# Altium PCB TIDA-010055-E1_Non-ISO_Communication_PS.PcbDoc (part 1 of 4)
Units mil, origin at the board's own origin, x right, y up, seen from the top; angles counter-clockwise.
Board outline 3937.01 x 3346.46 mil, 2 copper layers (Top Layer, Bottom Layer), stack 62 mil thick; 328 components, 142 nets, 761 pads, 214 vias.
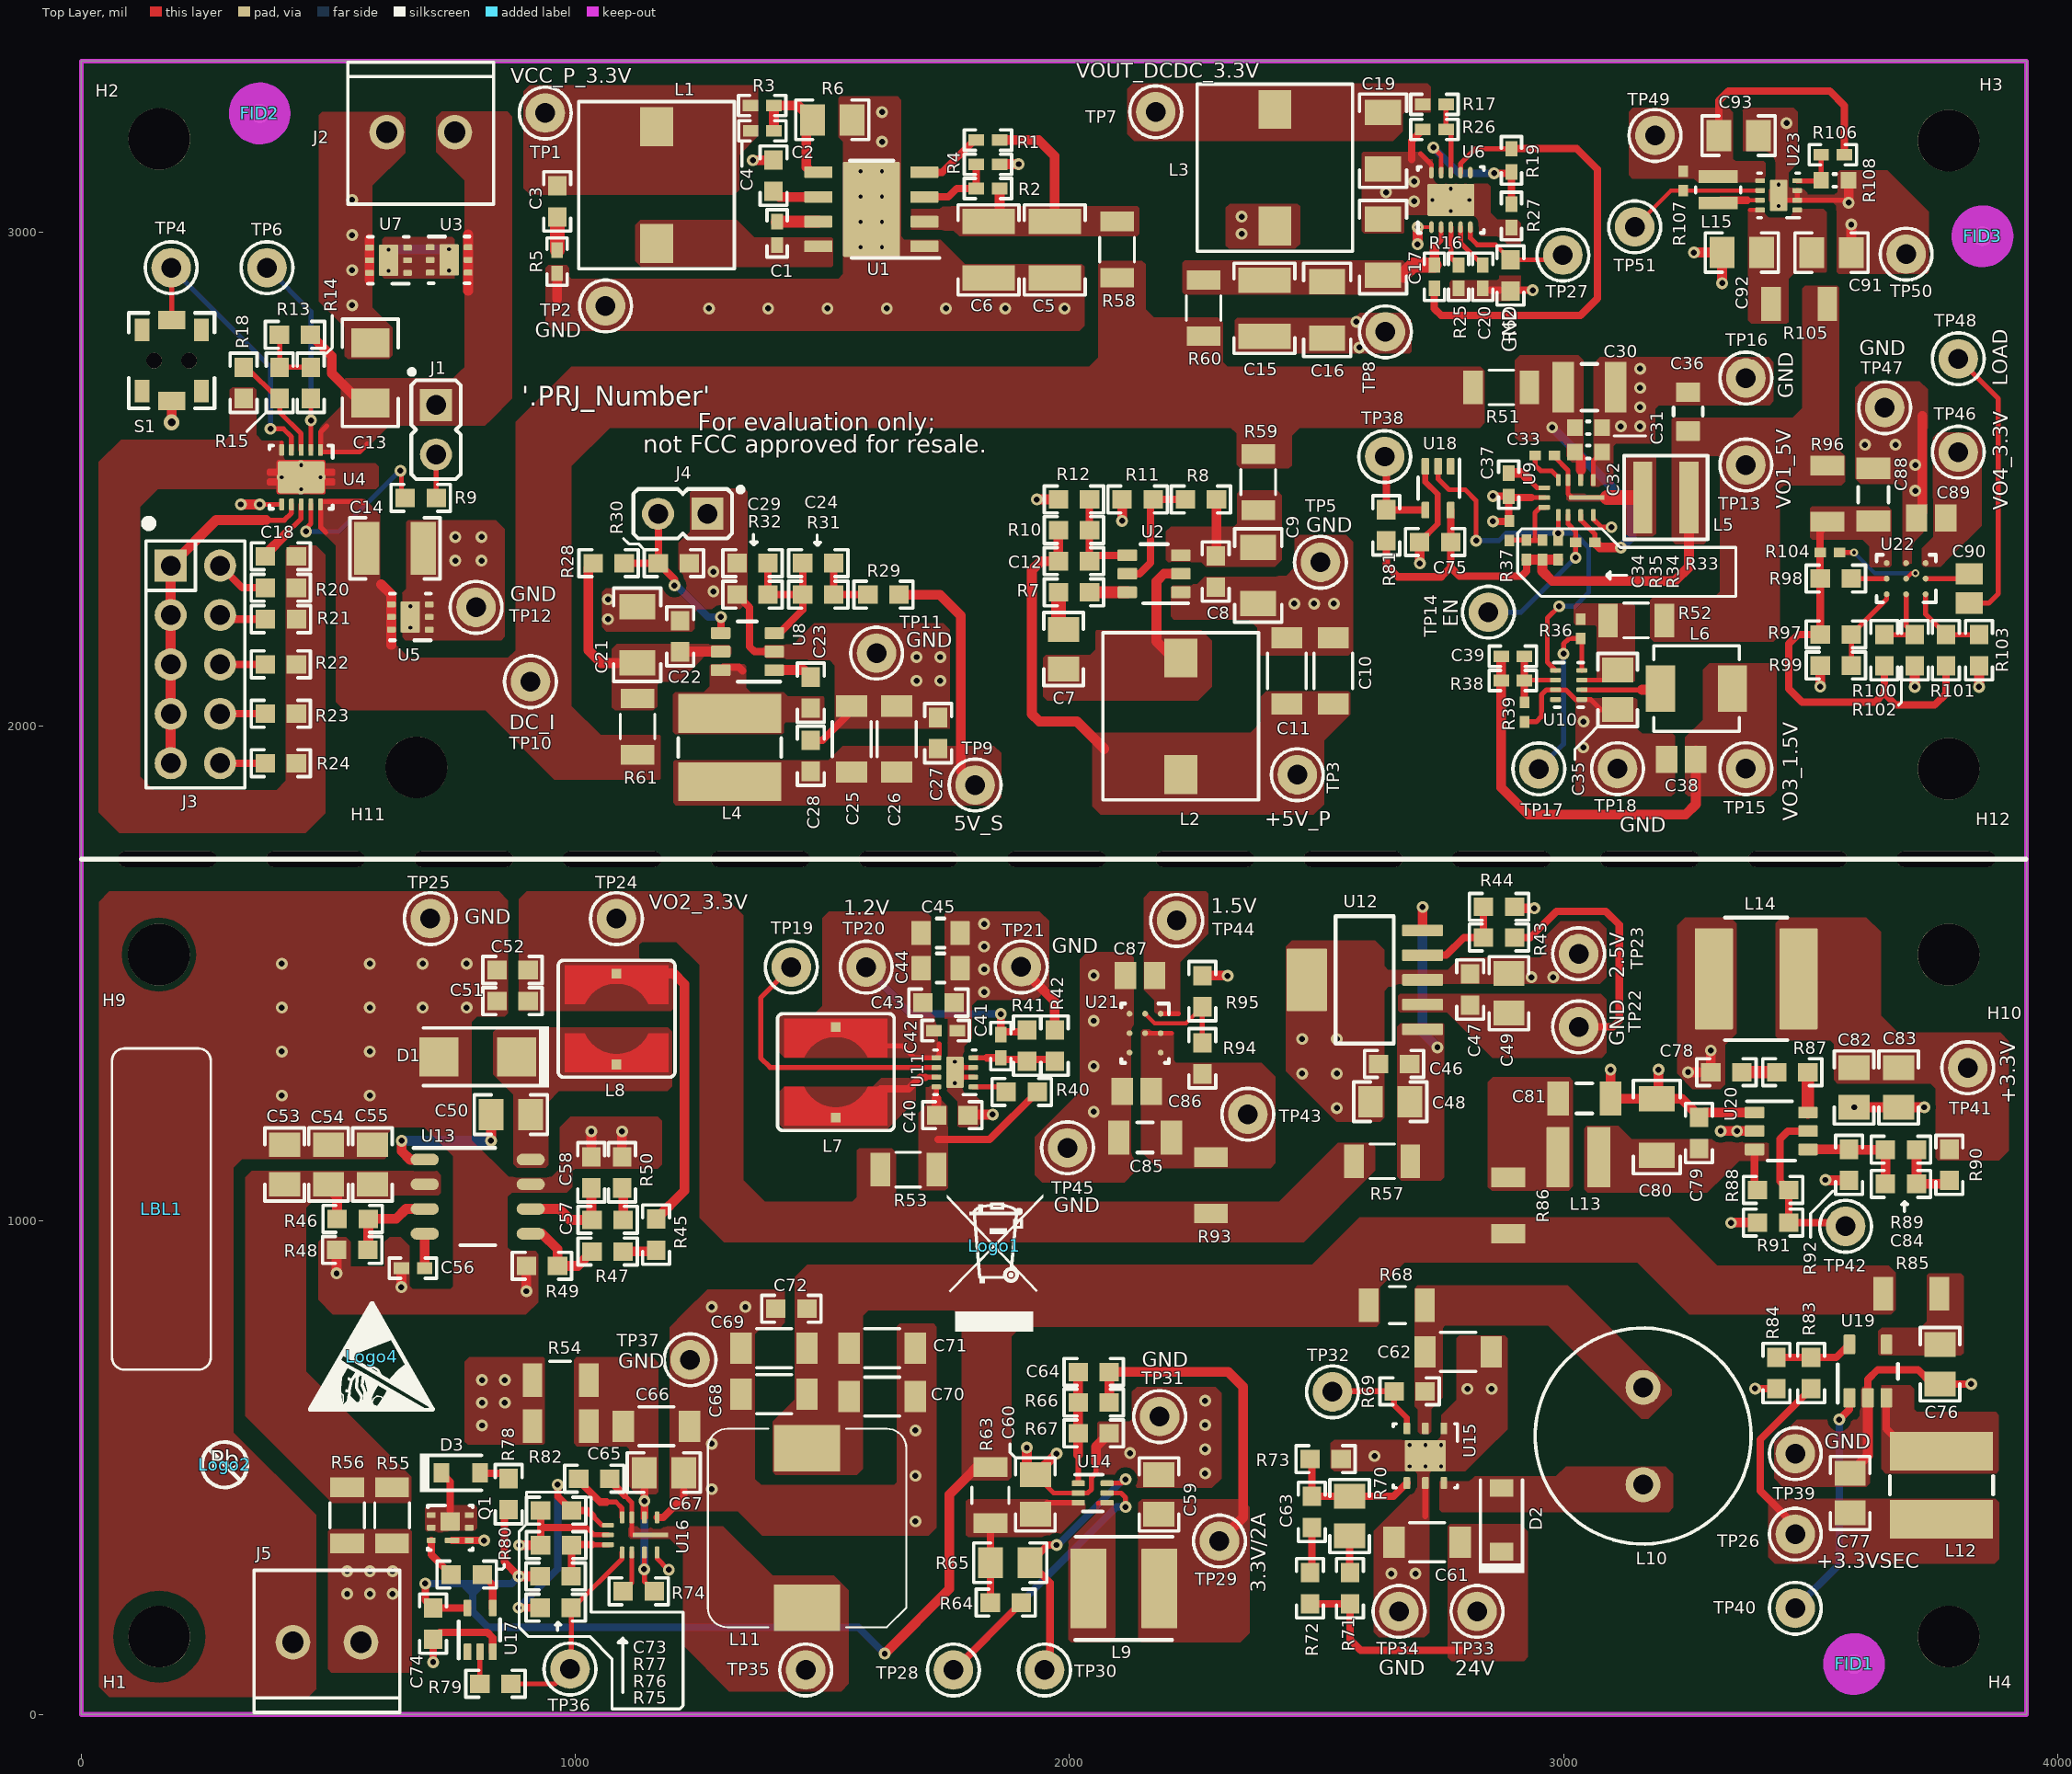
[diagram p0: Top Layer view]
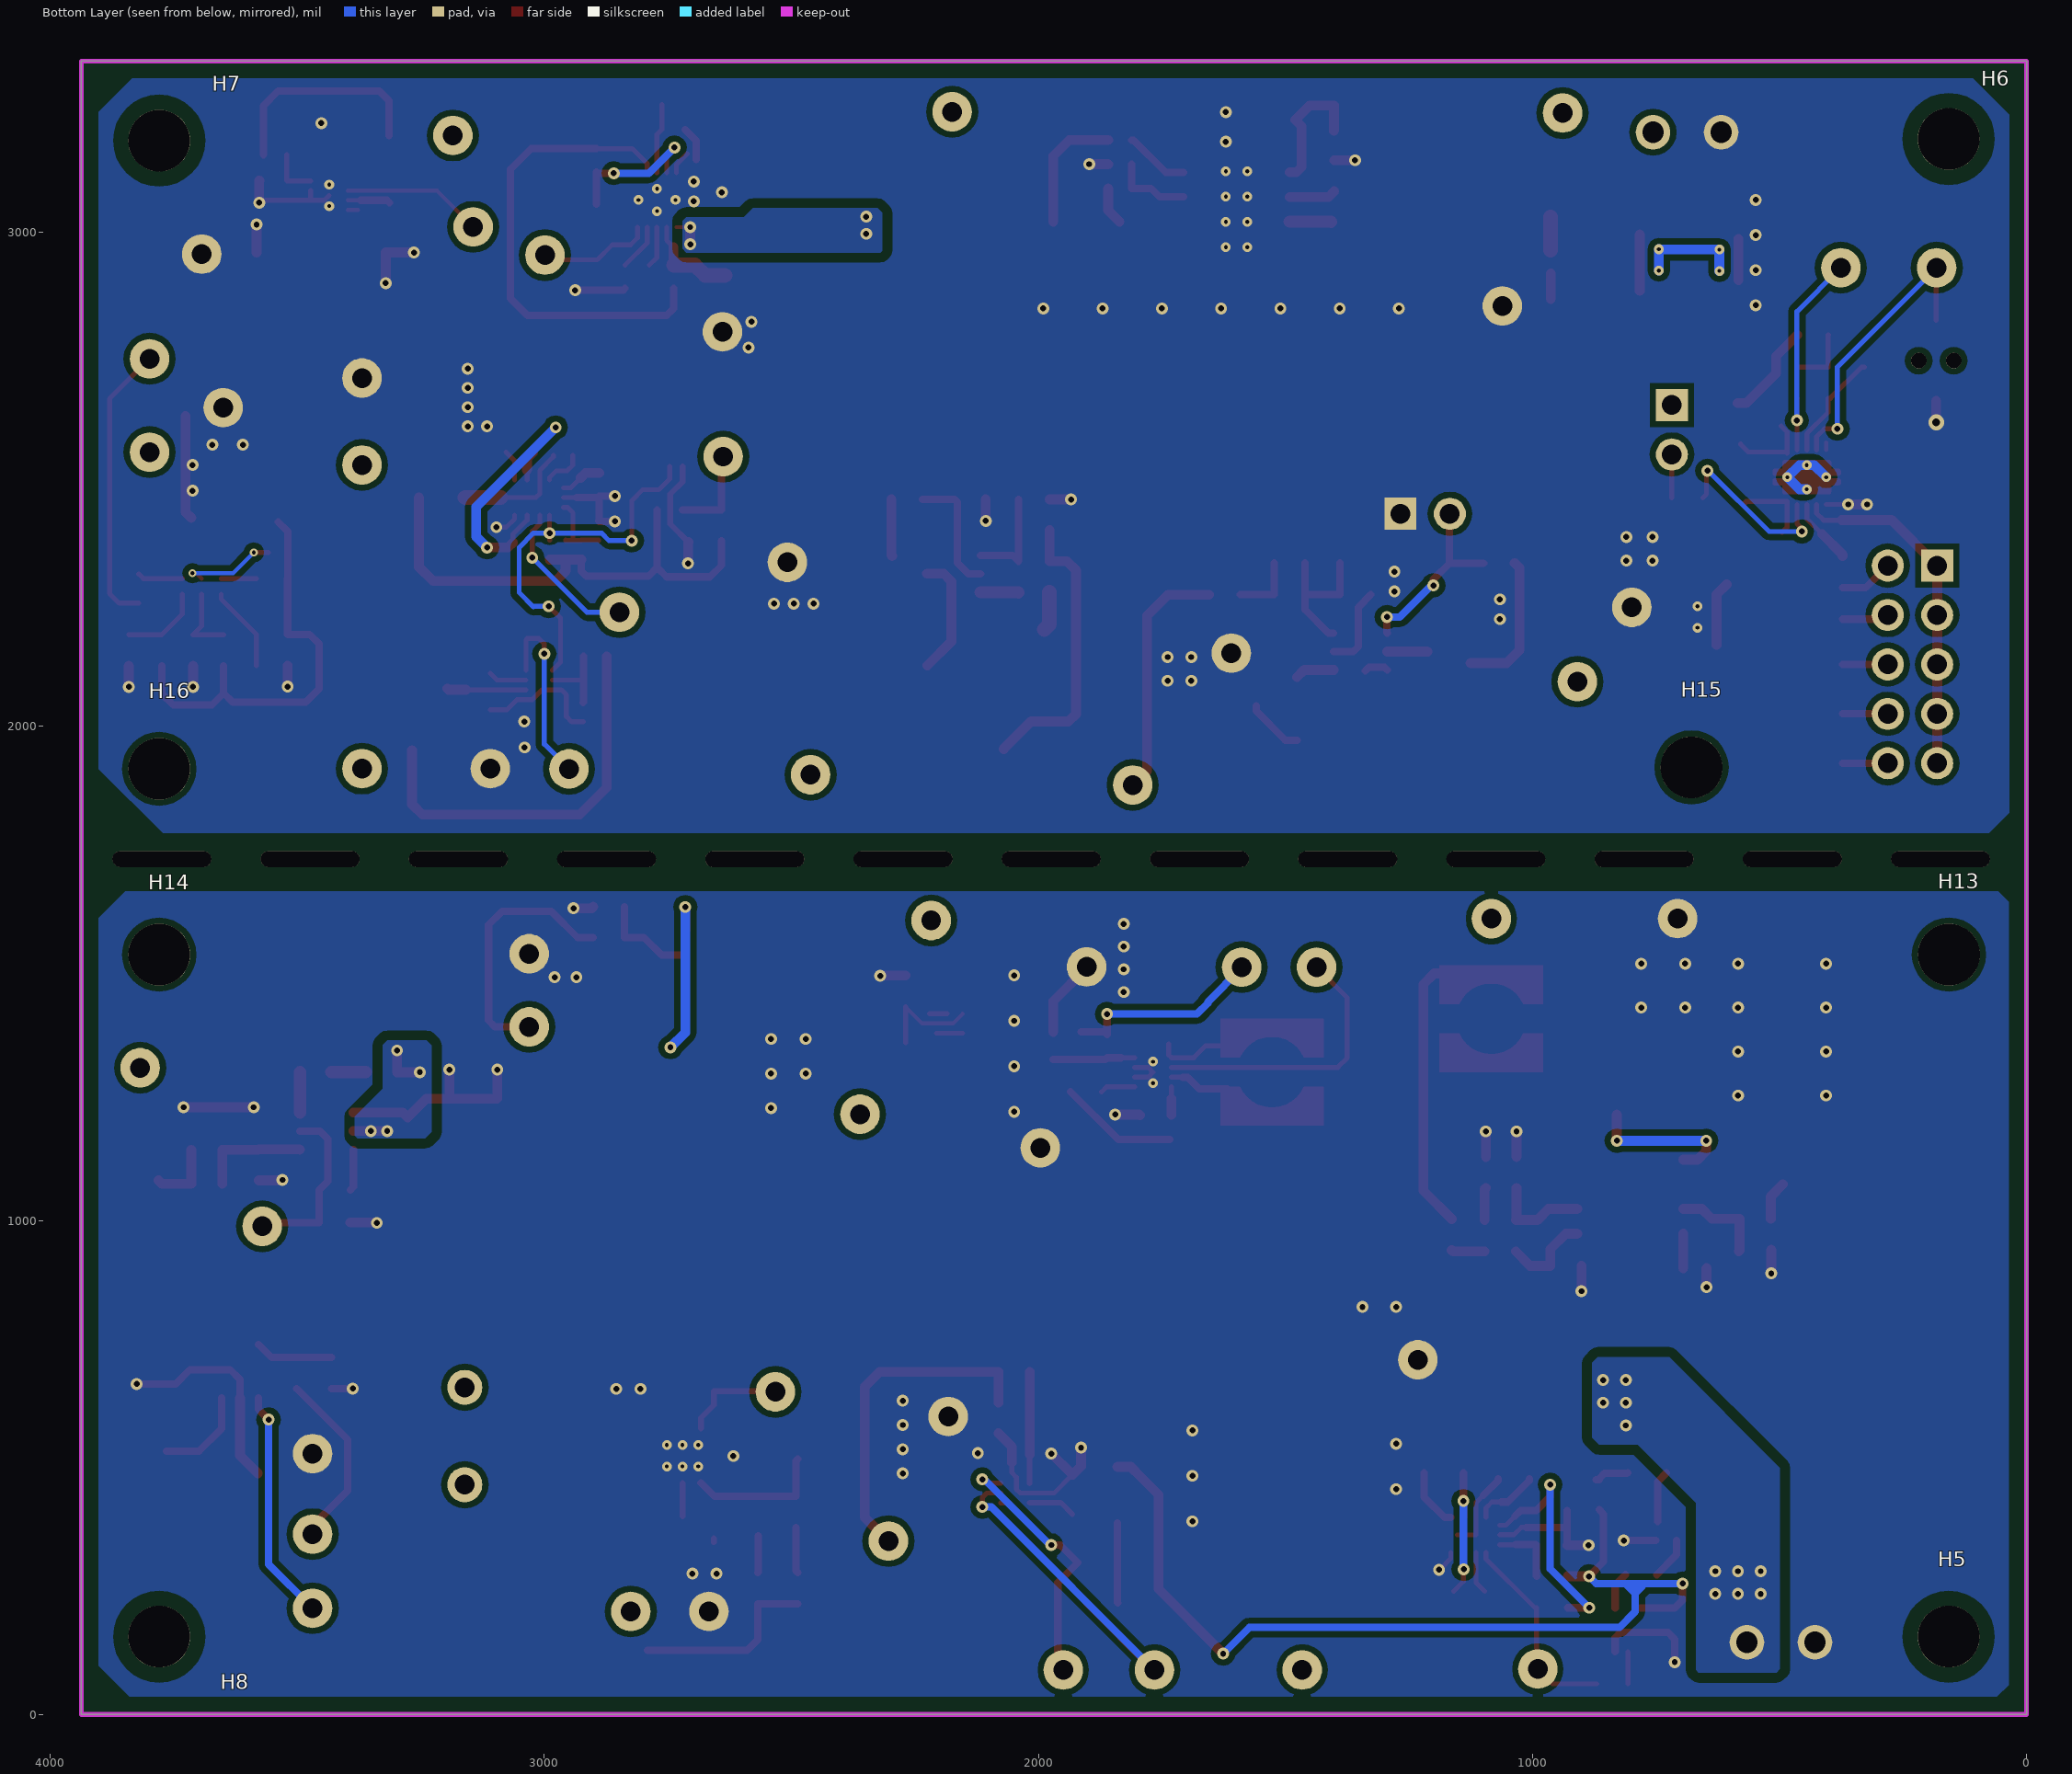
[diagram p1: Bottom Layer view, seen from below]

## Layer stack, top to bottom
Top Solder: solder mask 0.4, Solder Resist, Dk 3.5
Top Layer: signal copper 1.4
Dielectric1: core 59.2, FR-4 High Tg, Dk 4.8
Bottom Layer: signal copper 1.4
Bottom Solder: solder mask 0.4, Solder Resist, Dk 3.5

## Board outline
0,0 3937.01,0 3937.01,3346.46 0,3346.46

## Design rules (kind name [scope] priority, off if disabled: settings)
AcuteAngle [All] p1: minimum=4.50000000000000E+0001 checktracksonly=FALSE
AssemblyTestPointUsage [All] p1: valid=2
BoardOutlineClearance BoardOutlineClearance_MountingHoles [OnCopper and InComponentClass('Mounting Holes')] p1: gap=30 ignorepadtopadclearanceinfootprint=FALSE
BoardOutlineClearance BoardOutlineClearance_Poly [OnCopper and InPoly] p2: gap=25 ignorepadtopadclearanceinfootprint=FALSE
BoardOutlineClearance [OnCopper and Not InComponentClass('Logo') and not InComponentClass('FiducialMark') and not InRegion(1000,500,4000,800)] p3: gap=15 ignorepadtopadclearanceinfootprint=FALSE
Clearance Clearance_u23 [InPadClass('u23')] p1: gap=6 ignorepadtopadclearanceinfootprint=FALSE
Clearance Clearance_MH [InPadClass('MH') vs InPoly] p2: gap=30 ignorepadtopadclearanceinfootprint=FALSE except(0: Arc-Hole Track-Hole SMDPad-Hole THPad-Hole Via-Hole Fill-Hole Poly-Hole Region-Hole Text-Hole)
Clearance Clearance_Poly_poly [InPoly vs InPoly] p3: gap=20 ignorepadtopadclearanceinfootprint=FALSE except(0: Arc-Hole Track-Hole SMDPad-Hole THPad-Hole Via-Hole Fill-Hole Poly-Hole Region-Hole Text-Hole)
Clearance Clearance_Keepouts [IsKeepOut vs InPoly] p4: gap=30 ignorepadtopadclearanceinfootprint=FALSE except(0: Arc-Hole Track-Hole SMDPad-Hole THPad-Hole Via-Hole Fill-Hole Poly-Hole Region-Hole Text-Hole)
Clearance Clearance_Poly [InPolygon] p5: gap=12 ignorepadtopadclearanceinfootprint=FALSE
Clearance [All] p6: gap=7.87 ignorepadtopadclearanceinfootprint=FALSE except(0: Arc-SMDPad Arc-THPad Arc-Hole Track-Hole SMDPad-Hole THPad-Hole Via-Hole Fill-Hole Poly-Hole Region-Hole Text-Hole)
ComponentClearance ComponentClearance_MountingHoles_FiducialMarks [InComponentClass('Mounting Holes') vs InComponentClass('FiducialMark')] p1: gap=10 collisioncheckmode=3 verticalgap=10 showdistances=FALSE
ComponentClearance ComponentClearance_Shunt [InComponentClass('Header') vs InComponentClass('Shunt')] p2: gap=0 collisioncheckmode=3 verticalgap=0 showdistances=FALSE
ComponentClearance ComponentClearance_Logo [InComponentClass('Logo')] p3: gap=5 collisioncheckmode=3 verticalgap=5 showdistances=FALSE
ComponentClearance ComponentClearance_ScrewToNut [(HasFootprint('NY PMS 440 0025 PH')) vs (HasFootprint('Keystone_1902C'))] p4: gap=5 collisioncheckmode=3 verticalgap=10 showdistances=FALSE
ComponentClearance ComponentClearance_MountingHoles [InComponentClass('Mounting Holes')] p5: gap=250 collisioncheckmode=3 verticalgap=100000 showdistances=FALSE
ComponentClearance ComponentClearance_SmallPassives [HasFootprint('0201*') or HasFootprint('0402*') or HasFootprint('0508') or HasFootprint('0603*') or HasFootprint('0612') or HasFootprint('0805*') or HasFootprint('0815*') or HasFootprint('0830*') or HasFootprint('1206*') or HasFootprint('1210*') or HasFootprint('1808*') or HasFootprint('1812*') or HasFootprint('1825*') or HasFootprint('2010*') or HasFootprint('2220*') or HasFootprint('2225*') or HasFootprint('2512*') or HasFootprint('2728*') or HasFootprint('3518*') vs HasFootprint('0201*') or HasFootprint('0402*') or HasFootprint('0508') or HasFootprint('0603*') or HasFootprint('0612') or HasFootprint('0805*') or HasFootprint('0815*') or HasFootprint('0830*') or HasFootprint('1206*') or HasFootprint('1210*') or HasFootprint('1808*') or HasFootprint('1812*') or HasFootprint('1825*') or HasFootprint('2010*') or HasFootprint('2220*') or HasFootprint('2225*') or HasFootprint('2512*') or HasFootprint('2728*') or HasFootprint('3518*')] p6: gap=5 collisioncheckmode=3 verticalgap=5 showdistances=FALSE
ComponentClearance ComponentClearance_THtoSMT [IsThruComponent vs IsSMTComponent] p7: gap=5 collisioncheckmode=3 verticalgap=5 showdistances=FALSE
ComponentClearance ComponentClearance_THtoTH [IsThruComponent vs IsThruComponent] p8: gap=0 collisioncheckmode=3 verticalgap=10 showdistances=FALSE
ComponentClearance [All] p9: gap=10 collisioncheckmode=3 verticalgap=10 showdistances=FALSE
DiffPairsRouting [All] p1: maxlimit=100 minlimit=10 mostfreqgap=10 toplayer_minwidth=15 toplayer_maxwidth=15 toplayer_prefwidth=15 bottomlayer_minwidth=15 bottomlayer_maxwidth=15 bottomlayer_prefwidth=15 maxuncoupledlength=1000
FabricationTestPointUsage TestPointUsage [All] p1: valid=2 allowmultiple=FALSE
FabricationTestpoint Testpoint [All] p1: side=3 testpointundercomponent=TRUE minsize=40 maxsize=100 preferedsize=60 minholesize=0 maxholesize=40 preferedholesize=32 testpointgrid=1 allowsidetop=TRUE allowsidebottom=TRUE usegrid=TRUE gridtolerance=0.01
FanoutControl Fanout_LCC [IsLCC] p1: bgadir=Out bgaviamode=Centered fanoutstyle=Auto fanoutdirection=Alternating viagrid=1 // Fanout_LCC (Default Rule)
FanoutControl Fanout_BGA [IsBGA] p2: bgadir=Out bgaviamode=Centered fanoutstyle=Auto fanoutdirection=Alternating viagrid=1 // Fanout_BGA (Default Rule)
FanoutControl Fanout_Default [All] p4: bgadir=Out bgaviamode=Centered fanoutstyle=Auto fanoutdirection=Alternating viagrid=1 // Fanout_Default (Default Rule)
FanoutControl Fanout_Small [(CompPinCount < 5)] p5: bgadir=Out bgaviamode=Centered fanoutstyle=Auto fanoutdirection=OutThenIn viagrid=1 // Fanout_Small (Default Rule)
Height [All] p1: minheight=0 maxheight=99999 prefheight=500
HoleSize [All] p1: absolutevalues=TRUE maxlimit=251 minlimit=7.87 maxpercent=80.000 minpercent=20.000
MinimumAnnularRing MinimumAnnularRing_ThermalPadVias [IsVia and InAnyComponent] p1: minimumring=4
MinimumAnnularRing [All] p2: minimumring=4
MinimumSolderMaskSliver MinimumSolderMaskSliver_Logo [InComponentClass('Logo') vs InComponentClass('Logo')] p1: minsoldermaskwidth=0.7
MinimumSolderMaskSliver [All] p2: minsoldermaskwidth=3.5
PlaneClearance [All] p1: clearance=10
PlaneConnect [All] p1: planeconnectstyle=Relief reliefexpansion=10 reliefentries=4 reliefconductorwidth=10 reliefairgap=10
PolygonConnect PolygonConnectThermalVia [isvia] p1: connectstyle=Direct reliefconductorwidth=10 reliefentries=4 polygonreliefangle="90 Angle" airgapwidth=10
PolygonConnect PolygonConnectThermalPad [((ObjectKind = 'Pad') And (((Name Like 'U*') or (Name Like 'D*')) and (InComponentClass('TIDA-00183_pg-4_Driver') or InComponentClass('TIDA-00183_pg-5_OP_Connector')))) or ((ObjectKind = 'Pad') And (Name like 'U61*'))] p2: connectstyle=Direct reliefconductorwidth=10 reliefentries=4 polygonreliefangle="90 Angle" airgapwidth=10
PolygonConnect [All] p3: connectstyle=Direct reliefconductorwidth=10 reliefentries=4 polygonreliefangle="90 Angle" airgapwidth=5
RoutingVias ThermalPadVias [IsVia and InAnyComponent] p1: holewidth=7.87 width=19.68 viastyle="Through Hole" minholewidth=7.87 minwidth=19.68 maxholewidth=12.99 maxwidth=23.62
RoutingVias [All] p2: holewidth=16 width=32 viastyle="Through Hole" minholewidth=8 minwidth=16 maxholewidth=40 maxwidth=65
SilkToBoardRegionClearance [Not ((IsComment or IsDesignator) And (Hide <> 'False')) and not InRegion(1000,500,4000,800)] p1:
SilkToSilkClearance SilkToSilkClearance_Pb-FreeLogo [(HasFootprint('Pb-Free_Overlay_Medium') OR HasFootprint('Pb-Free_Overlay_Small')) vs (HasFootprint('Pb-Free_Overlay_Medium') OR HasFootprint('Pb-Free_Overlay_Small'))] p1: silktosilkclearance=0
SilkToSilkClearance [All] p2: silktosilkclearance=4
SilkToSolderMaskClearance SilkToComponentPadClearance [IsPad and InAnycomponent] p1: minsilkscreentomaskgap=5 clearancetoexposedcopper=TRUE
SilkToSolderMaskClearance "Silk to Solder Mask Opening" [All] p2: minsilkscreentomaskgap=4 clearancetoexposedcopper=FALSE
SolderMaskExpansion [All] p1: expansion=1.97
Width [All] p1: maxlimit=100 minlimit=6 preferedwidth=10 checkconnectedcopper=TRUE
13 further rules are at their usual default settings.

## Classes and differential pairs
component class FiducialMark: FID1 FID2 FID3
component class Label: LBL1
pad class MH: H1-1 H2-1 H3-1 H4-1 H5-0 H6-0 H7-0 H8-0
component class TIDA-010055-E1_Non-ISO_Communication_PS_EVM_Hardware_Pg6: FID1 FID2 FID3 H1 H2 H3 H4 H5 H6 H7 H8 H9 H10 H11 H12 H13 H14 H15 H16 LBL1 Logo1 Logo2 Logo3 Logo4 ZZ1 ZZ2 ZZ3 ZZ4
component class AssemblyNote: ZZ1 ZZ2 ZZ3 ZZ4
component class Header: J1 J3 J4
component class TIDA-010055-E1_Non-ISO_Communication_PS_Pg3: C1 C2 C3 C4 C5 C6 C7 C8 C9 C10 C11 C12 C13 C14 C15 C16 C17 C18 C19 C20 C21 C22 C23 C24 C25 C26 C27 C28 C29 J1 J2 J3 J4 L1 L2 L3 L4 R1 R2 R3 R4 R5 R6 R7 R8 R9 R10 R11 R12 R13 R14 R15 R16 R17 R18 R19 R20 R21 R22 R23 R24 R25 R26 R27 R28 R29 R30 R31 R32 R58 R59 R60 R61 R62 S1 TP1 TP2 TP3 TP4 TP5 TP6 TP7 TP8 TP9 TP10 TP11 TP12 TP27 U1 U2 U3 U4 U5 U6 U7 U8
component class TIDA-010055-E1_Non-ISO_Communication_PS_Pg4: C30 C31 C32 C33 C34 C35 C36 C37 C38 C39 C75 C88 C89 C90 C91 C92 C93 L5 L6 L15 R33 R34 R35 R36 R37 R38 R39 R51 R52 R81 R96 R97 R98 R99 R100 R101 R102 R103 R104 R105 R106 R107 R108 TP13 TP14 TP15 TP16 TP17 TP18 TP38 TP46 TP47 TP48 TP49 TP50 TP51 U9 U10 U18 U22 U23
component class TIDA-010055-E1_Non-ISO_Communication_PS_Pg5: C59 C60 C61 C62 C63 C64 C65 C66 C67 C68 C69 C70 C71 C72 C73 C74 C76 C77 C78 C79 C80 C81 C82 C83 C84 D2 D3 L9 L10 L11 L12 L13 L14 Q1 R54 R63 R64 R65 R66 R67 R68 R69 R70 R71 R72 R73 R74 R75 R76 R77 R78 R79 R80 R82 R83 R84 R85 R86 R87 R88 R89 R90 R91 R92 TP26 TP28 TP29 TP30 TP31 TP32 TP33 TP34 TP35 TP36 TP37 TP39 TP40 TP41 TP42 U14 U15 U16 U17 U19 U20
component class TIDA-010055-E1_Non-ISO_Communication_PS_Pg6: C40 C41 C42 C43 C44 C45 C46 C47 C48 C49 C50 C51 C52 C53 C54 C55 C56 C57 C58 C85 C86 C87 D1 J5 L7 L8 R40 R41 R42 R43 R44 R45 R46 R47 R48 R49 R50 R53 R55 R56 R57 R93 R94 R95 TP19 TP20 TP21 TP22 TP23 TP24 TP25 TP43 TP44 TP45 U11 U12 U13 U21
pad class u23: U23-1 U23-2 U23-3 U23-4 U23-5 U23-6 U23-7

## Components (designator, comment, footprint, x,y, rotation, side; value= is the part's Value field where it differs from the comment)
C1 "C0402C103K4PAC7867" 0402 1408.13,2997.88 r270 top value=0.01uF
C2 "CL10A105KO8NNNC" 0603 1401,3114.55 r90 top value=1uF
C3 "GRM188R60J106ME47D" 0603 963,3062.55 r270 top value=10uF
C4 "C0402C751J5GAC7867" 0402 1378.38,3205.55 r0 top value=750pF
C5 "C3225X7R2A225K230AB" 1210_270 1970,2964.55 r90 top value=2.2uF
C6 "C3225X7R2A225K230AB" 1210_270 1836,2964.55 r90 top value=2.2uF
C7 "C0805C104K3RACTU" 0805_HV 1988,2156.3 r90 top value=0.1uF
C8 "CL10B104KA8NNNC" 0603 2296,2313.3 r270 top value=0.1uF
C9 "CL31B106KAHNNNE" 1206 2382,2305.3 r270 top value=10uF
C10 "GCM31CR71A226KE02" 1206_190#1 2534,2112.3 r90 top value=22uF
C11 "GCM31CR71A226KE02" 1206_190#1 2440,2112.3 r90 top value=22uF
C12 "06033C101KAT2A" 0603 2009,2334.3 r0 top value=100pF
C13 "C3216X7R2A105K160AA" 1206_180M 584.78,2715.35 r90 top value=1uF
C14 "C3225X7R2A225K230AB" 1210_270 634.78,2360.35 r0 top value=2.2uF
C15 "CL32B106KBJNNWE" 1210_270 2394.5,2846 r270 top value=10uF
C16 "UMK316B7225KL-T" 1206 2521.5,2842.71 r270 top value=2.2uF
C17 "C3216X7R2A105K160AA" 1206 2634.5,2970.04 r90 top value=1uF
C18 "C0603C223K4RACTU" 0603 403.78,2344.35 r0 top value=0.022uF
C19 "CL31B226KPHNNNE" 1206 2634.5,3185.54 r270 top value=22uF
C20 "CL05B473KO5NNNC" 0402 2836.5,2910 r270 top value=0.047uF
C21 "UMK316B7225KL-T" 1206 1125.21,2185.32 r90 top value=2.2uF
C22 "C0603X124K5RAC7867" 0603 1212.21,2182.32 r90 top value=0.1uF
C23 "C0603X124K5RAC7867" 0603 1476.41,2068.23 r270 top value=0.1uF
C24 "06035A220JAT2A" 0603 1491.43,2330.49 r180 top value=22pF
C25 "CL31B226MPHNNNE" 1206_180 1559.21,1974.32 r90 top value=22uF
C26 "CL31B226MPHNNNE" 1206_180 1650.21,1974.32 r90 top value=22uF
C27 "C0603X124K5RAC7867" 0603 1734.21,1986.32 r270 top value=0.1uF
C28 "UMK107BJ105KA-T" 0603 1476.21,1940.32 r90 top value=1uF
C29 "06035A220JAT2A" 0603 1358.43,2330.49 r180 top value=22pF
C30 "CIN2" 1210_220L 3052.2,2686.3 r180 top value=4.7uF
C31 "CIN3" 0603L 3050.2,2604.3 r0 top value=0.047uF
C32 "CIN1" 0603L 3050.2,2555.3 r0 top value=0.047uF
C33 "CB" 0402L 2962,2548.1 r0 top value=0.1uF
C34 "CFF" 0402L 2925,2357.1 r90 top value=20pF
C35 "C2012X7R1A475M125AC" 0805_HV 3109.37,2073.83 r270 top value=4.7uF
C36 "CL21A226KQCLRNC" 0805_HV1 3252,2637.1 r90 top value=22uF
C37 "C1005X7S1A105K050BC" 0402 2889,2489.1 r270 top value=1uF
C38 "GRM21BR71A106ME51L" 0805L 3238,1933.4 r180 top value=10uF
C39 "GRM1555C1H121FA01D" 0402 2897.37,2141.83 r0 top value=120pF
C40 "CL10A106MQ8NNNC" 0603 1762.99,1212.75 r0 top value=10uF
C41 "CL05C220JB51PNC" 0402 1860.99,1352.75 r270 top value=22pF
C42 "GCM155R71H471KA37D" 0402 1749.39,1384.23 r0 top value=470pF
C43 "885012106018" 0603 1734.99,1440.75 r0 top value=2.2uF
C44 "CL21A226KQCLRNC" 0805_HV1 1738.99,1510.75 r0 top value=22uF
C45 "CL21A226KQCLRNC" 0805_HV1 1738.99,1581.75 r0 top value=22uF
C46 "06031A101GAT2A" 0603 2656.98,1316.85 r0 top value=100pF
C47 "06031A101GAT2A" 0603 2811,1467.25 r270 top value=100pF
C48 "C2012X5R1E106K085AC" 0805_HV 2649.2,1240.42 r0 top value=10uF
C49 "C2012X5R1E106K085AC" 0805_HV 2889.47,1459.85 r270 top value=10uF
C50 "C0805C104K3RACTU" 0805_HV 869.22,1214.16 r180 top value=0.1uF
C51 "GRM188R60J476ME15D" 0603 872.72,1443.9 r180 top value=47uF
C52 "GRM188R60J476ME15D" 0603 872.72,1506.9 r180 top value=47uF
C53 "C2012X7R1E475K125AB" 0805_HV 411.22,1113.16 r90 top value=4.7uF
C54 "C2012X7R1E475K125AB" 0805_HV 500.22,1113.16 r90 top value=4.7uF
C55 "08055C103JAT2A" 0805_HV 589.22,1113.16 r90 top value=0.01uF
C56 "C0402C103K4PAC7867" 0402 671.22,903.16 r180 top value=0.01uF
C57 "06035A102KAT2A" 0603 1065.22,1001.16 r0 top value=1000pF
C58 "06035A470KAT2A" 0603 1032.22,1097.16 r90 top value=47pF
C59 "GRM21BR71A106KE51L" 0805_HV 2181.01,445.19 r90 top value=10uF
C60 "C2012X7R1V475K125AC" 0805_HV 1931.01,445.19 r90 top value=4.7uF
C61 "CL31B106KBHNNNE" 1206_180 2723.87,348.54 r180 top value=10uF
C62 "UMK316AB7475KL-T" 1206_190#2 2726.47,787 r90 top value=4.7uF
C63 "GRM188R71H331KA01D" 0603 2490.37,410.05 r270 top value=330pF
C64 "06035A6R8CAT2A" 0603 2049.01,693.19 r180 top value=6.8pF
C65 "CL10B104KB8NNNC" 0603 1038,477.4 r0 top value=0.1uF
C66 "C3216X7R1V106K160AC" 1206_180 1164,583.4 r0 top value=10uF
C67 "UMK212B7224KG-T" 0805_HV 1179,489.4 r0 top value=0.22uF
C68 "EMK316BB7226ML-T" 1206_190#1 1402,648.4 r180 top value=22uF
C69 "EMK316BB7226ML-T" 1206_190#1 1402,741.4 r180 top value=22uF
C70 "EMK316BB7226ML-T" 1206_190#1 1621,643.4 r0 top value=22uF
C71 "EMK316BB7226ML-T" 1206_190#1 1621,741.4 r0 top value=22uF
C72 "EMK107B7104KA-T" 0603 1437,821.4 r180 top value=0.1uF
C73 "885012206052" 0603 961,412.6 r180 top value=1uF
C74 "GMK107BJ104KAHT" 0603 712,184 r270 top value=0.1uF
C75 "C0603C104K5RECAUTO" 0603 2740,2373 r180 top value=0.1uF
C76 "C2012X5R1E475K125AB" 0805_HV 3762,709 r270 top value=4.7uF
C77 "CL21A226KQCLRNC" 0805_HV 3580,448 r90 top value=22uF
C78 "C0603C104K9RAC7867" 0603 3329.5,1300 r180 top value=0.1uF
C79 "885012206071" 0603 3274,1177 r90 top value=0.1uF
C80 "GMK316AB7106KL" 1206 3188.61,1188.94 r90 top value=10uF
C81 "CL31A476MPHNNNE" 1206_190L 3042,1247 r0 top value=47uF
C82 "CL21A226MPCLRNC" 0805_HV 3588,1269 r270 top value=22uF
C83 "CL21A226MPCLRNC" 0805_HV 3678,1269 r270 top value=22uF
C84 "CL10C220JB8NNNC" 0603 3683,1074 r180 top value=22pF
C85 "CL31A476MPHNNNE" 1206_190L 2153,1168 r180 top value=47uF
C86 "GRM21BR71A106ME51L" 0805L 2136,1261 r180 top value=10uF
C87 "GRM21BR71A106ME51L" 0805L 2143,1496 r180 top value=10uF
C88 "CL31A476MPHNNNE" 1206_190L 3627,2469 r90 top value=47uF
C89 "GRM21BR71A106ME51L" 0805L 3744,2422 r180 top value=10uF
C90 "GRM21BR71A106ME51L" 0805L 3821,2279 r270 top value=10uF
C91 "JMK212BJ226KG-T" 0805_HV 3542.31,2958.72 r0 top value=22uF
C92 "JMK212BJ226KG-T" 0805_HV 3361,2959 r180 top value=22uF
C93 "JMK212BJ226KG-T" 0805_HV 3354.31,3195.72 r0 top value=22uF
D1 "B340A-13-F" SMA 802.48,1331.16 r180 top value=40V
D2 "MBR130T1G" SOD-123 2874.4,394 r90 top value=30V
D3 "LG M67K-G1J2-24-Z" LG_M67K_Green 768,489 r0 top value=Green
FID1 "Fiducial" Fiducial10-30 3588,102 r0 top
FID2 "Fiducial" Fiducial10-30 360.9,3240.62 r90 top
FID3 "Fiducial" Fiducial10-30 3848,2992 r90 top
H1 "NSP-4-3-01" B_F_PMSSS4400025PH#1 157.48,157.48 r0 top
H2 "NSP-4-3-01" B_F_PMSSS4400025PH#2 157.48,3188.98 r0 top
H3 "NSP-4-3-01" B_F_PMSSS4400025PH#1 3779.53,3185.57 r0 top
H4 "NSP-4-3-01" B_F_PMSSS4400025PH#1 3779.53,157.48 r0 top
H5 "1902E" Keystone_1902E 157.48,157.48 r180 bottom
H6 "1902E" Keystone_1902E 156.96,3188.98 r180 bottom
H7 "1902E" Keystone_1902E 3779.53,3185.75 r180 bottom
H8 "1902E" Keystone_1902E 3779.53,157.48 r180 bottom
H9 "NSP-4-3-01" B_F_PMSSS4400025PH#1 157,1538 r0 top
H10 "NSP-4-3-01" B_F_PMSSS4400025PH#1 3779.53,1538 r0 top
H11 "NSP-4-3-01" B_F_PMSSS4400025PH#1 678,1917 r0 top
H12 "NSP-4-3-01" B_F_PMSSS4400025PH#1 3779.53,1914 r0 top
H13 "1902E" Keystone_1902E 157,1538 r180 bottom
H14 "1902E" Keystone_1902E 3779.53,1538 r180 bottom
H15 "1902E" Keystone_1902E 678,1917 r180 bottom
H16 "1902E" Keystone_1902E 3779.53,1914 r180 bottom
J1 "PBC02SAAN" Sullins_PBC02SAAN 717.78,2600.35 r0 top
J2 "1751248" CONN_1751248 687,3202.4 r180 top
J3 "PEC05DAAN" CONN_PEC05DAAN 230.78,2125.35 r270 top
J4 "PBC02SAAN" Sullins_PBC02SAAN 1217.21,2430.32 r270 top
J5 "1751248" CONN_1751248 497,146 r0 top
L1 "744777233" WE-PD-M 1164,3095.4 r90 top value=330uH
L2 "7447779122" WE-PD-M 2225,2020.3 r270 top value=22uH
L3 "744777218" WE-PD-M 2415.68,3130.74 r90 top value=180uH
L4 "74408943150" WE-SPC_4838 1312.21,1957.05 r270 top value=15uH
L5 "74438357100" WE-MAPI_4030 3207,2463.1 r0 top value=10uH
L6 "74437324015" IND_WE-LHMI-4020 3269,2076.4 r0 top value=1.5uH
L7 "744042001" WE-TPC-M1 1527.18,1300.23 r90 top value=1uH
L8 "744042006" WE-TPC-M1 1083.33,1408.17 r90 top value=6.8uH
L9 "LQH5BPN2R2NT0L" LQH5BPN_20 2110.01,255.19 r0 top value=2.2uH
L10 "7447471220" WE-TIS-1111 3161,563.57 r270 top value=22uH
L11 "7447798111" WE-PDF_1064 1469,377.4 r90 top value=11uH
L12 "74408943220" WE-SPC_4838 3765,464 r270 top value=22uH
L13 "ABG03A15M4R7" ABG03A15 3030,1128 r0 top value=4.7uH
L14 "ABG06A45M3R3" ABG06A45 3390,1489 r0 top value=3.3uH
L15 "VLS2012ET-R47N" VLS2012ET 3313,3086 r90 top value=470nH
LBL1 "Size: 0.65\" x 0.20 \"" Label_650x200 162,1023 r90 top
Logo1 "WEEE logo" WEEE_Minimum 1847.55,948 r0 top
Logo2 "Pb-Free Symbol" Pb-Free_Overlay_Small 290,505.4 r0 top
Logo3 "FCC disclaimer" FCC_disclaimer_stacked -204.28,2457.06 r90 top
Logo4 "ESD Susceptible" ESD_Overlay_Medium 588,724 r0 top
Q1 "CSD17571Q2" DQK0006C 746.61,378 r0 top value=30V
R1 "CRCW040288K7FKED" 0402 1835,3186.55 r0 top value=88.7k
R2 "CRCW040251K1FKED" 0402 1835,3088.55 r0 top value=51.1k
R3 "CRCW040210K0FKED" 0402 1378,3256.55 r180 top value=10.0k
R4 "CRCW040213K0FKED" 0402 1835,3137.55 r180 top value=13.0k
R5 "CRCW04022R15FKED" 0402 963,2940.55 r90 top value=2.15
R6 "CRCW08056K19FKEA" 0805_HV 1520,3227.55 r180 top value=6.19k
R7 "CRCW06030000Z0EA" 0603 2009,2271.3 r180 top value=0
R8 "CRCW0603510KJNEA" 0603 2266,2459.3 r0 top value=510k
R9 "CRCW060349K9FKEA" 0603 686.78,2462.35 r0 top value=49.9k
R10 "CRCW0603100KFKEA" 0603 2009,2397.3 r180 top value=100k
R11 "CRCW0603118KFKEA" 0603 2138,2459.3 r0 top value=118k
R12 "CRCW060313K3FKEA" 0603 2009,2459.3 r0 top value=13.3k
R13 "CRCW0603887KFKEA" 0603 432.32,2792.35 r0 top value=887k
R14 "CRCW06030000Z0EA" 0603 464.32,2695.35 r270 top value=0
R15 "CRCW060329K4FKEA" 0603 401.32,2695.35 r90 top value=29.4k
R16 "CRCW04022M00FKED" 0402 2738.5,2910 r90 top value=2.00Meg
R17 "CRCW0402499KFKED" 0402 2738.5,3259 r180 top value=499k
R18 "CRCW060334K0FKEA" 0603 328.32,2695.35 r90 top value=34.0k
R19 "CRCW0402357KFKED" 0402 2894.5,3145.54 r90 top value=357k
R20 "CRCW06037K50FKEA" 0603 403.78,2280.35 r180 top value=7.50k
R21 "CRCW060313K3FKEA" 0603 404,2217 r180 top value=13.3k
R22 "CRCW060326K7FKEA" 0603 403.78,2125.35 r180 top value=26.7k
R23 "CRCW060344K2FKEA" 0603 403.78,2025.35 r180 top value=44.2k
R24 "CRCW0603267KFKEA" 0603 403.78,1925.35 r180 top value=267k
R25 "CRCW0402100KFKED" 0402 2787.5,2910 r90 top value=100k
R26 "CRCW0402294KFKED" 0402 2738.5,3208 r0 top value=294k
R27 "CRCW040234K0FKED" 0402 2894.5,3033 r90 top value=34.0k
R28 "CRCW0603402KFKEA" 0603 1067.21,2330.32 r180 top value=402k
R29 "CRCW060349R9FKEA" 0603 1623.43,2266.49 r0 top value=49.9
R30 "CRCW0603133KFKEA" 0603 1199.21,2330.32 r180 top value=133k
R31 "CRCW0603102KFKEA" 0603 1491.43,2266.49 r0 top value=102k
R32 "CRCW060325K5FKEA" 0603 1358.43,2266.49 r0 top value=25.5k
R33 "CRCW0402100KFKED" 0402L 3044,2372.1 r0 top value=100k
R34 "RPG" 0402L 2989,2357.1 r90 top value=100k
R35 "CRCW0402100KFKED" 0402L 2957,2357.1 r270 top value=100k
R36 "RPG2" 0402L 3034.68,2197.52 r90 top value=10.0k
R37 "CRCW040224K9FKED" 0402L 2890,2396.1 r270 top value=24.9k
R38 "ERJ-2RKF1503X" 0402 2897.37,2092.83 r180 top value=150k
R39 "RFBB2" 0402L 2921.37,2028.83 r90 top value=100k
R40 "CRCW06030000Z0EA" 0603 1903.52,1260.23 r180 top value=0
R41 "RC0603FR-0764K9L" 0603 1913.99,1353.75 r90 top value=64.9k
R42 "RC0603FR-0738K3L" 0603 1969.99,1353.75 r270 top value=38.3k
R43 "CRCW06034K22FKEA" 0603 2869.47,1572.85 r0 top value=4.22k
R44 "CRCW06034K02FKEA" 0603 2869.47,1634.85 r180 top value=4.02k
R45 "CRCW06030000Z0EA" 0603 1163.22,971.16 r90 top value=0
R46 "CRCW0603332KFKEA" 0603 549.22,1003.16 r180 top value=332k
R47 "CRCW060310K2FKEA" 0603 1065.22,937.16 r0 top value=10.2k
R48 "RC0603FR-0768K1L" 0603 548.12,940.31 r0 top value=68.1k
R49 "CRCW06033K24FKEA" 0603 932.22,908.16 r0 top value=3.24k
R50 "RC0603FR-0729K4L" 0603 1094.22,1097.16 r270 top value=29.4k
R51 "5108" 5108 2874,2686 r180 top value=0
R52 "5108" 5108 3147,2214.4 r0 top value=0
R53 "5108" 5108 1673.81,1102.6 r180 top value=0
R54 "5108" 5108 970,677 r180 top value=0
R55 "5108" 5108 629,403 r270 top value=0
R56 "5108" 5108 538,403 r270 top value=0
R57 "5108" 5108 2633,1119.64 r180 top value=0
R58 "5108" 5108 2096.13,2964.88 r90 top value=0
R59 "5108" 5108 2382,2494.3 r270 top value=0
R60 "5108" 5108 2271.5,2846.62 r90 top value=0
R61 "5108" 5108 1125.73,1999.51 r90 top value=0
R62 "ERJ-3GEY0R00V" 0603 2892.68,2912.85 r90 top value=0
R63 "5108" 5108 1840.01,444.19 r270 top value=0
R64 "ERA-3AEB104V" 0603 1871.01,226.19 r0 top value=100k
R65 "RR1220P-4753-D-M" 0805_HV 1880.01,307.19 r180 top value=475k
R66 "RC0603FR-07453KL" 0603 2049.01,631.19 r0 top value=453k
R67 "ERA-3AEB104V" 0603 2049.01,569.19 r180 top value=100k
R68 "5108" 5108 2662.4,828 r0 top value=0
R69 "ERA-3AEB104V" 0603 2688.4,654 r180 top value=100k
R70 "RT0805BRD07182KL" 0805_HV 2566.87,401.54 r270 top value=182k
R71 "RMCF0603ZT0R00" 0603 2567.87,255.54 r90 top value=0
R72 "RMCF0603ZT0R00" 0603 2486.94,255.54 r90 top value=0
R73 "RG1608P-103-B-T5" 0603 2518.37,516.96 r180 top value=10.0k
R74 "RMCF0603ZT0R00" 0603 1128,249.4 r0 top value=0
R75 "ERA-3AEB104V" 0603 960,216 r0 top value=100k
R76 "ERA-3AEB104V" 0603 960,279.6 r180 top value=100k
R77 "RT0603BRD0724K9L" 0603 961,342.6 r0 top value=24.9k
R78 "CRCW0603300RJNEA" 0603 865,446 r270 top value=300
R79 "RMCF0603ZT0R00" 0603 838,62 r180 top value=0
R80 "CRCW0603300RJNEA" 0603 780,283 r0 top value=300
R81 "RG1608P-473-B-T5" 0603 2641,2407 r270 top value=47.0k
R82 "5108" 5108 970,583.39 r180 top value=0
R83 "CRCW060361K9FKEA" 0603 3501,691 r270 top value=61.9k
R84 "CRCW060320K0FKEA" 0603 3431,691 r90 top value=20.0k
R85 "5108" 5108 3704,852 r0 top value=0
R86 "5108" 5108 2888,1030 r90 top value=0
R87 "CRCW06030000Z0EA" 0603 3463,1300 r180 top value=0
R88 "CRCW060380K6FKEA" 0603 3424.12,1061.69 r180 top value=80.6k
R89 "CRCW060333K2FKEA" 0603 3683,1143 r0 top value=33.2k
R90 "CRCW060351R0JNEA" 0603 3781,1112.5 r90 top value=51
R91 "CRCW060349K9FKEA" 0603 3424.12,995.69 r0 top value=49.9k
R92 "RCG060310K0FKEA" 0603 3578,1112.5 r90 top value=10.0k
R93 "5108" 5108 2286,1071 r270 top value=0
R94 "CRCW06030000Z0EA" 0603 2269,1328 r270 top value=0
R95 "CRCW06030000Z0EA" 0603 2269,1464 r270 top value=0
R96 "5108" 5108 3534,2471 r270 top value=0
R97 "CRCW06030000Z0EA" 0603 3551,2186 r180 top value=0
R98 "CRCW06030000Z0EA" 0603 3551,2299 r0 top value=0
R99 "CRCW06030000Z0EA" 0603 3551,2123 r0 top value=0
R100 "CRCW06030000Z0EA" 0603 3649,2154 r270 top value=0
R101 "CRCW06030000Z0EA" 0603 3774,2154 r270 top value=0
R102 "CRCW06030000Z0EA" 0603 3711,2154 r90 top value=0
R103 "CRCW06030000Z0EA" 0603 3841,2154 r90 top value=0
R104 "RPG2" 0402L 3539,2352 r0 top value=10.0k
R105 "5108" 5108 3477,2855 r180 top value=0
R106 "CRCW0402487KFKED" 0402 3545,3157 r0 top value=487k
R107 "RC0402FR-071ML" 0402L 3242,3104 r90 top value=1.00Meg
R108 "RC0603FR-07162KL" 0603L 3549,3105 r180 top value=162k
S1 "PTS820 J20M SMTR LFS" SW_PTS820 182.74,2740.34 r90 top
TP1 "5000" KEYSTONE5000 939,3241.4 r0 top
TP2 "5001" Keystone5001 1061,2850.88 r0 top
TP3 "5000" KEYSTONE5000 2461,1902 r270 top
TP4 "5002" Keystone5002#1 181.78,2928.35 r0 top
TP5 "5001" Keystone5001 2508,2332 r270 top
TP6 "5002" Keystone5002#1 375.78,2928.35 r0 top
TP7 "5000" KEYSTONE5000 2174.5,3244 r90 top
TP8 "5001" Keystone5001 2639.5,2798.62 r90 top
TP9 "5000" KEYSTONE5000 1809,1881.29 r0 top
TP10 "5000" KEYSTONE5000 909,2090.4 r90 top
TP11 "5001" Keystone5001 1609.41,2148.23 r0 top
TP12 "5001" Keystone5001 798.78,2240.82 r90 top
TP13 "5000" KEYSTONE5000 3369,2529.1 r0 top
TP14 "5002" Keystone5002#1 2848,2231 r0 top
TP15 "5000" KEYSTONE5000 3369,1914.4 r270 top
TP16 "5001" Keystone5001 3369,2705.1 r0 top
TP17 "5002" Keystone5002#2 3095,2032 r0 top
TP18 "5001" Keystone5001 3109.37,1914.4 r0 top
TP19 "5002" Keystone5002#1 1437,1512.64 r270 top
TP20 "5000" KEYSTONE5000 1588.52,1512.64 r270 top
TP21 "5001" Keystone5001 1902.39,1513.03 r270 top
TP22 "5000" KEYSTONE5000 3030.47,1391.85 r270 top
TP23 "5001" Keystone5001 3030.47,1539.85 r0 top
TP24 "5000" KEYSTONE5000 1083,1610.64 r90 top
TP25 "5001" Keystone5001 706.22,1610.79 r90 top
TP26 "5000" Keystone5000 3469,365 r0 top value=Red
TP27 "5002" Keystone5002#1 2998.68,2953.85 r90 top
TP28 "5002" Keystone5002#1 1765,90 r180 top
TP29 "5000" Keystone5000 2303.54,350.96 r180 top
TP30 "5002" Keystone5002#1 1949.54,90 r90 top
TP31 "5001" Keystone5001 2182.54,602.96 r180 top
TP32 "5002" Keystone5002#1 2532.4,653 r90 top
TP33 "5000" Keystone5000 2824.87,208.54 r90 top
TP34 "5001" Keystone5001 2666.87,208.54 r90 top
TP35 "5002" Keystone5002#1 1466,90 r270 top
TP36 "5002" Keystone5002#1 989,92 r270 top
TP37 "5001" Keystone5001 1232,718 r270 top
TP38 "5002" Keystone5002#1 2638,2546 r90 top
TP39 "5001" Keystone5001 3469,528 r0 top
TP40 "5002" Keystone5002#1 3469,215 r0 top
TP41 "5000" Keystone5000 3818,1309 r135 top value=Red
TP42 "5002" Keystone5002#1 3571,988 r225 top
TP43 "5000" Keystone5000 2361,1215 r0 top
TP44 "5000" Keystone5000 2217,1607 r0 top
TP45 "5001" Keystone5001 1996,1147 r0 top
TP46 "5000" Keystone5000 3799,2555 r0 top
TP47 "5001" Keystone5001 3650,2645 r0 top
TP48 "5000" Keystone5000 3799,2744 r0 top
TP49 "5000" Keystone5000 3185,3196 r180 top
TP50 "5001" Keystone5001 3693.31,2955.72 r180 top
TP51 "5000" Keystone5000 3144,3011 r0 top
U1 "LM5017MRX/NOPB" DDA0008B_N 1599,3046.55 r180 top
U2 "TPS54202DDCR" DDC0006A_N 2171.13,2308.9 r180 top
U3 "TVS3300DRVR" DRV0006A 744.33,2944.06 r0 top
U4 "TPS26624DRCR" DRC0010J#1 444.78,2504.35 r270 top
U5 "TVS2700DRVR" DRV0006A 665.78,2221.35 r180 top
U6 "LM5165DRCR" DRC0010J#2 2771.9,3065.54 r90 top
U7 "TVS3300DRVR" DRV0006A 621.61,2943.4 r180 top
U8 "TPS560430XFDBVR" DBV0006A_N 1348.21,2151.32 r180 top
U9 "LMR36006BRNXR" RNX0012B 3016,2463.1 r270 top
U10 "TPS62821DLC" DLC0008A 3010.37,2083.83 r0 top
U11 "TLV62080DSGR" DSG0008A 1767.99,1299.75 r180 top
U12 "TPS73801DCQR" DCQ0006A_N 2597.47,1486.85 r180 top
U13 "TPS54331D" D0008A_N 802.22,1048.16 r0 top
U14 "TLV62569PDRL" DRL0006A 2047.01,448.19 r0 top
U15 "LM2735XSD/NOPB" NGG0006A 2720.27,523.66 r270 top
U16 "LMR33630ARNXR" RNX0012B 1121,363.4 r270 top
U17 "SN74LVC1G17DCKR" DCK0005A_N 807,171 r90 top
U18 "SN74LVC1G07DCKR" DCK0005A_N 2746,2482 r270 top
U19 "TPS560200DBVR" DBV0005A_N 3616,695 r90 top value=TPS560200D
U20 "TPS561201DDCR" DDC0006A_N 3440.61,1180.94 r0 top
U21 "TPS826721SIPR" SIP0008A 2153,1379 r270 top
U22 "TPS82740ASIPR" SIP0009F 3693.37,2299 r180 top
U23 "TLV62084DSGR" DSG0008A 3435.31,3074.72 r180 top
ZZ1 "This Assembly Note is for PCB labels only" AssemblyNoteLabel 40.81,3845.4 r0 top
ZZ2 "These assemblies are ESD sensitive, ESD precautions shall be observed." AssemblyNote 37.81,3739.52 r0 top
ZZ3 "These assemblies must be clean and free from flux and all contaminants. Use of no clean flux is not acceptable." AssemblyNote 37.81,3650.96 r0 top
ZZ4 "These assemblies must comply with workmanship standards IPC-A-610 Class 2, unless otherwise specified." AssemblyNote 37.81,3562.4 r0 top

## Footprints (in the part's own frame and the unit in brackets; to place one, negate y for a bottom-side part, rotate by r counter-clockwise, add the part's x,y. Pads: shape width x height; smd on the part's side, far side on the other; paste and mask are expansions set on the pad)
0402 [mm] "0402 from SM-752 data"
  rect 0.8x0.6 smd: 1(-0.6,0) 2(0.6,0)
  silkscreen extent -1.22,-0.52 1.22,0.52, body extent -0.55,-0.3 0.55,0.3, height 0.6
0402L [mm] "0402 from SM-752 data"
  rect 0.6x0.5 smd: 1(-0.5,0) 2(0.5,0)
  body extent -0.55,-0.3 0.55,0.3, height 0.6
0603 [mm] "0603 from SM-752 data"
  rect 1x0.95 smd: 1(-0.8,0) 2(0.8,0)
  silkscreen extent -1.52,-0.69 1.52,0.69, body extent -0.87,-0.47 0.87,0.47, height 1
0603L [mm] "0603 from SM-752 data"
  rect 0.8x0.85 smd: 1(-0.7,0) 2(0.7,0)
  silkscreen extent -0.07,-0.33 0.07,0.33, body extent -0.87,-0.47 0.87,0.47, height 1
0805_HV [mil] "0805 with 30mil clearance between pads"
  rect 50x63 smd: 1(-40,0) 2(40,0)
  silkscreen extent -74,-40 74,40, body extent -43,-29 43,29, height 57
0805_HV1 [mm] "Custom footprint based on analyzing multiple manufacturer recommendations"
  rrect10% 1x1.25 smd: 1(-1,0) 2(1,0)
  silkscreen extent -0.2,-0.75 0.2,0.75, body extent -1.1,-0.72 1.1,0.73, height 1.45
0805L [mm] "0805 from SM-752 data"
  rect 1.1x1.4 smd: 1(-0.75,0) 2(0.75,0)
  body extent -1.1,-0.72 1.1,0.72, height 1.45
1206 [mm] "1206 from SM-752 data"
  rect 1.3x1.85 smd: 1(-1.45,0) 2(1.45,0)
  silkscreen extent -2.4,-1.21 2.4,1.21, body extent -1.7,-0.9 1.7,0.9, height 1.35
1206_180 [mm] "1206_180"
  rect 1.1x1.6 smd: 1(-1.7,0) 2(1.7,0)
  silkscreen extent -0.9,-1 0.9,1, body extent -1.75,-0.95 1.75,0.95, height 1.8
1206_180M [mm] "1206_180"
  rect 1.5x1.95 smd: 1(-1.55,0) 2(1.55,0)
  silkscreen extent -2.76,-1.44 2.76,1.44, body extent -1.75,-0.95 1.75,0.95, height 1.8
1206_190#1 [mm] "1206_190"
  rect 1.1x1.6 smd: 1(-1.7,0) 2(1.7,0)
  silkscreen extent -0.9,-1 0.9,1, body extent -1.75,-0.95 1.75,0.95, height 1.9
1206_190#2 [mm] "1206_190"
  rect 1.6x1.1 smd: 1(-1.346,0.176) 2(-1.346,-3.224)
  silkscreen extent -2.35,-2.42 -0.35,-0.62, body extent -2.3,-3.27 -0.4,0.23, height 1.9
1206_190L [mm] "1206_190"
  rect 1.1x1.75 smd: 1(-1.35,0) 2(1.35,0)
  silkscreen extent -0.4,-0.77 0.4,0.77, body extent -1.75,-0.95 1.75,0.95, height 1.9
1210_220L [mm] "1210"
  rect 1.1x2.6 smd: 1(-1.35,0) 2(1.35,0)
  silkscreen extent -0.4,-1.2 0.4,1.2, body extent -1.7,-1.35 1.7,1.35, height 2.2
1210_270 [mm] "1210"
  rect 1.3x2.7 smd: 1(-1.45,0) 2(1.45,0)
  silkscreen extent -2.32,-1.57 2.32,1.57, body extent -1.7,-1.35 1.7,1.35, height 2.7
5108 [mm] "Keystone"
  rect 1.01x1.73 smd: 1(-1.445,0) 2(1.445,0)
  silkscreen extent -0.64,-0.89 0.64,0.89, body extent -1.52,-0.85 1.52,0.85, height 0.71
ABG03A15 [mm] "SMD, 2-Leads, Body 3x3mm"
  rrect8% 1.2x3.1 smd: 1(-1.05,0) 2(1.05,0)
  body extent -1.6,-1.6 1.6,1.6, height 1.5
ABG06A45 [mm] "SMD, 2-Leads, Body 6x6mm"
  rrect5% 1.95x5.2 smd: 1(-2.175,0) 2(2.175,0)
  silkscreen extent -1.6,-3.15 1.6,3.15, body extent -3.15,-3.15 3.15,3.15, height 4.5
AssemblyNote [mil] "Assembly Note"
AssemblyNoteLabel [mil] "Assembly Note for PCB Labels"
B_F_PMSSS4400025PH#1 [mil] "MACHINE SCREW PAN PHILLIPS 4-40"
  round 125 hole 125 unplated: 1(0,0)
  body extent -109,-109 110,110, height 79
B_F_PMSSS4400025PH#2 [mil] "MACHINE SCREW PAN PHILLIPS 4-40"
  round 125 hole 125 unplated mask+10: 1(0,0)
  body extent -109,-109 110,110, height 79
CONN_1751248 [mil] "Phoenix Contact"
  round 70 hole 43.31: 1(-68.9,0) 2(68.9,0)
  silkscreen extent -148,-142 148,146, body extent -148,-142 148,146, height 335
CONN_PEC05DAAN [mm] "SULLINS"
  rect 1.65x1.65 hole 1.016 mask+0: 1(-5.08,-1.27)
  round 1.65 hole 1.016 mask+0: 2(-5.08,1.27) 3(-2.54,-1.27) 4(-2.54,1.27) 5(0,-1.27) 6(0,1.27) 7(2.54,-1.27) 8(2.54,1.27) 9(5.08,-1.27) 10(5.08,1.27)
  silkscreen extent -7.45,-2.6 6.35,2.54, body extent -6.35,-2.54 6.35,2.54, height 8.38
D0008A_N [mm] "SOIC, 8-Leads, Body 4.9x3.9mm, Pitch 1.27mm, IPC Medium Density"
  oval 1.45x0.6 smd: 1(-2.725,1.905) 2(-2.725,0.635) 3(-2.725,-0.635) 4(-2.725,-1.905) 5(2.725,-1.905) 6(2.725,-0.635) 7(2.725,0.635) 8(2.725,1.905)
  silkscreen extent -3.3,-2.5 0.9,2.5, body extent -3,-2.45 3,2.45, height 1.63
DBV0005A_N [mm] "SOT23, 5-Leads, Body 2.9x1.6mm, Pitch 0.95mm, Lead Span 2.8mm, IPC Medium Density"
  rrect17% 1x0.6 smd: 1(-1.375,0.95) 2(-1.375,0) 3(-1.375,-0.95) 4(1.375,-0.95) 5(1.375,0.95)
  silkscreen extent -1.63,-1.55 0.38,1.55, body extent -1.42,-1.46 1.42,1.46, height 1.09
DBV0006A_N [mm] "SOT23, 6-Leads, Body 2.9x1.6mm, Pitch 0.95mm, Lead Span 2.8mm, IPC Medium Density"
  rrect17% 1x0.6 smd: 1(-1.375,0.95) 2(-1.375,0) 3(-1.375,-0.95) 4(1.375,-0.95) 5(1.375,0) 6(1.375,0.95)
  silkscreen extent -1.68,-1.55 0.5,1.55, body extent -1.42,-1.46 1.42,1.46, height 1.12
DCK0005A_N [mm] "SOT353, 5-Leads, Body 2x1.3mm, Pitch 0.65mm, Lead Span 2.1mm, IPC Medium Density"
  rrect25% 0.85x0.4 smd: 1(-1.125,0.65) 2(-1.125,0) 3(-1.125,-0.65) 4(1.125,-0.65) 5(1.125,0.65)
  silkscreen extent -1.48,-1.02 0.55,1.1, body extent -1.14,-1 1.14,1, height 0.95
DCQ0006A_N [mm] "SOT223, 6-Leads, Body 6.6x7.3mm (max), Pitch 1.27mm, IPC Medium Density"
  rrect17% 2.1x0.6 smd: 1(-2.975,2.54) 2(-2.975,1.27) 3(-2.975,0) 4(-2.975,-1.27) 5(-2.975,-2.54)
  rrect5% 2.1x3.2 smd: 6(2.975,0)
  silkscreen extent -1.5,-3.27 1.5,3.27, body extent -3.54,-3.25 3.54,3.25, height 1.8
DDA0008B_N [mm] "SOIC, 8-Leads, Body 4.9x3.9mm, Pitch 1.27mm, Exposed Pad, IPC Medium Density"
  rrect17% 1.45x0.6 smd: 1(-2.725,1.905) 2(-2.725,0.635) 3(-2.725,-0.635) 4(-2.725,-1.905) 5(2.725,-1.905) 6(2.725,-0.635) 7(2.725,0.635) 8(2.725,1.905)
  rrect7% 2.95x4.9 smd paste-1.5 mask-1.5: 9(0,0)
  rrect4% 2.71x3.4 on Top Paste: 9(0,0)
  rrect4% 2.71x3.4 on Top Solder: 9(0,0)
  silkscreen extent -3.5,-2.5 1.1,2.5, body extent -3.01,-2.45 3.01,2.45, height 1.57
DDC0006A_N [mm]
  rrect17% 1x0.6 smd: 1(-1.375,0.95) 2(-1.375,0) 3(-1.375,-0.95) 4(1.375,-0.95) 5(1.375,0) 6(1.375,0.95)
  silkscreen extent -1.75,-1.52 0.7,1.53, body extent -1.43,-1.48 1.43,1.49, height 0.92
DLC0008A [mm] "QFN-8 (2.0mmX1.5mm)"
  rrect40% 0.55x0.25 smd: 1(-0.675,0.75) 2(-0.675,0.25) 3(-0.675,-0.25) 4(-0.675,-0.75) 5(0.675,-0.75) 6(0.675,-0.25) 7(0.675,0.25) 8(0.675,0.75)
  silkscreen extent -0.75,-1.15 0.75,1.15, body extent -0.8,-1.05 0.8,1.05, height 1.02
DQK0006C [mm] "WSON"
  rrect12% 0.9x0.86 on Top Paste: 0(0,0.325)
  rrect34% 0.7x0.29 on Top Paste: 0(0.095,-0.65)
  rrect33% 0.45x0.3 smd: 1(-0.975,0.65) 2(-0.975,0) 3(-0.975,-0.65) 4(0.975,-0.65) 5(0.975,0) 6(0.975,0.65)
  rrect33% 0.75x0.3 smd paste-0.15: 7(0.095,-0.65)
  rrect11% 1x0.95 smd paste-0.5: 8(0,0.325)
  silkscreen extent -1.15,-1.15 1.15,1.15, body extent -1,-1 1,1, height 0.82
DRC0010J#1 [mm] "SON, 10-Leads, Body 3x3mm, Pitch 0.5mm, Thermal Pad 2.4x1.65mm, TI Recommended"
  rrect40% 0.6x0.25 smd: 1(-1.4,1) 2(-1.4,0.5) 3(-1.4,0) 4(-1.4,-0.5) 5(-1.4,-1) 6(1.4,-1) 7(1.4,-0.5) 8(1.4,0) 9(1.4,0.5) 10(1.4,1)
  rrect40% 0.25x0.34 on Top Paste: 11(-0.25,1.53) 11(-0.25,-1.53) 11(0.25,1.53) 11(0.25,-1.53)
  rrect9% 1.5x1.06 on Top Paste: 11(0,0.63) 11(0,-0.63)
  rrect12% 1.65x2.4 smd paste-1 mask-2: 11(0,0)
  Top Layer region: -0.775,-1.25 -0.425,-1.25 -0.425,-1.65 -0.417,-1.688 -0.396,-1.721 -0.363,-1.742 -0.325,-1.75 -0.325,-1.75 -0.325,-1.75 -0.175,-1.75 -0.175,-1.75 -0.137,-1.742 -0.104,-1.721 -0.083,-1.688 -0.075,-1.65 -0.075,-1.65 -0.075,-1.25 0.075,-1.25 0.075,-1.65 0.083,-1.688 0.104,-1.721 0.137,-1.742 0.175,-1.75 0.175,-1.75 0.175,-1.75 0.325,-1.75 0.325,-1.75 0.363,-1.742 0.396,-1.721 0.417,-1.688 0.425,-1.65 0.425,-1.65 0.425,-1.25 0.775,-1.25 0.813,-1.242 0.846,-1.221 0.867,-1.188 0.875,-1.15 0.875,-1.15 0.875,1.15 0.867,1.188 0.846,1.221 0.813,1.242 0.775,1.25 0.775,1.25 0.425,1.25 0.425,1.65 0.417,1.688 0.396,1.721 0.363,1.742 0.325,1.75 0.325,1.75 0.175,1.75 0.137,1.742 0.104,1.721 0.083,1.688 0.075,1.65 0.075,1.65 0.075,1.25 -0.075,1.25 -0.075,1.65 -0.083,1.688 -0.104,1.721 -0.137,1.742 -0.175,1.75 -0.175,1.75 -0.325,1.75 -0.363,1.742 -0.396,1.721 -0.417,1.688 -0.425,1.65 -0.425,1.65 -0.425,1.25 -0.775,1.25 -0.813,1.242 -0.846,1.221 -0.867,1.188 -0.875,1.15 -0.875,1.15 -0.875,-1.15 -0.867,-1.188 -0.846,-1.221 -0.813,-1.242 -0.775,-1.25
  silkscreen extent -1.63,-1.63 1.63,1.63, body extent -1.5,-1.5 1.5,1.5, height 0.77
DRC0010J#2 [mm] "SON, 10-Leads, Body 3x3mm, Pitch 0.5mm, Thermal Pad 2.4x1.65mm, TI Recommended"
  rrect100% 0.6x0.24 smd: 1(-1.4,1) 2(-1.4,0.5) 3(-1.4,0) 4(-1.4,-0.5) 5(-1.4,-1) 6(1.4,-1) 7(1.4,-0.5) 8(1.4,0) 9(1.4,0.5) 10(1.4,1)
  rrect6% 1.65x2.4 smd paste-0.825: 11(0,0)
  silkscreen extent -1.7,-1.7 1.7,1.7, body extent -1.5,-1.5 1.5,1.5, height 0.77
DRL0006A [mm] "SOTFL, 6-Flat Leads, Body 1.2x1.6x0.6mm, Pitch 0.5mm, TI recommended"
  rrect33% 0.67x0.3 smd: 1(-0.74,0.5) 2(-0.74,0) 3(-0.74,-0.5) 4(0.74,-0.5) 5(0.74,0) 6(0.74,0.5)
  silkscreen extent -0.9,-0.95 0.5,0.95, body extent -0.8,-0.8 0.8,0.8, height 0.61
DRV0006A [mm] "SON, 6-Leads, Body 2x2mm, Pitch 0.65mm, Thermal Pad 1.6x1mm, TI Recommended"
  rrect33% 0.45x0.3 smd: 1(-0.975,0.65) 2(-0.975,0) 3(-0.975,-0.65) 4(0.975,-0.65) 5(0.975,0) 6(0.975,0.65)
  rrect14% 1x0.7 on Top Paste: 7(0,-0.45) 7(0,0.45)
  rrect10% 1x1.6 smd paste-0.5: 7(0,0)
  silkscreen extent -1.05,-1.2 1.05,1.2, body extent -1.05,-1.05 1.05,1.05, height 0.81
DSG0008A [mm] "SON, 8-Leads, Body 2x2mm, Pitch 0.5mm, Thermal Pad 1.6x0.9mm, TI Recommended"
  rrect40% 0.5x0.25 smd: 1(-0.95,0.75) 2(-0.95,0.25) 3(-0.95,-0.25) 4(-0.95,-0.75) 5(0.95,-0.75) 6(0.95,-0.25) 7(0.95,0.25) 8(0.95,0.75)
  rrect14% 0.9x0.7 on Top Paste: 9(0,0.45) 9(0,-0.45)
  rrect11% 0.9x1.6 smd paste-0.45: 9(0,0)
  silkscreen extent -1.07,-1.15 1.07,1.15, body extent -1,-1 1,1, height 0.77
ESD_Overlay_Medium [mil]
  silkscreen extent -127,-109 125,110
FCC_disclaimer_stacked [mil]
Fiducial10-30 [mm]
  round 1 smd mask+1: 1(0,0)
  Top Layer keep-out circle w1.678: c0,0 r0.75
IND_WE-LHMI-4020 [mm] "WERTH"
  rect 1.5x2.4 smd: 1(-1.85,0) 2(1.85,0)
  silkscreen extent -2.2,-2.2 2.2,2.2, body extent -2.15,-2.15 2.15,2.15, height 2
KEYSTONE5000 [mil] "For Keystone 500x miniature loop terminals"
  round 80 hole 40: 1(0,0)
  silkscreen extent -52,-52 52,52, body extent -49,-49 49,49, height 182
Keystone5000 [mil] "For Keystone 500x miniature loop terminals"
  round 80 hole 40: 1(0,0)
  silkscreen extent -52,-52 52,52, body extent -49,-49 49,49, height 182
Keystone5001 [mil] "For Keystone 500x miniature loop terminals"
  round 80 hole 40: 1(0,0)
  silkscreen extent -52,-52 52,52, body extent -49,-49 49,49, height 182
Keystone5002#1 [mil] "For Keystone 500x miniature loop terminals"
  round 80 hole 40: 1(0,0)
  silkscreen extent -52,-52 52,52, body extent -49,-49 49,49, height 182
Keystone5002#2 [mil] "For Keystone 500x miniature loop terminals"
  round 80 hole 40: 1(-145,-118)
  silkscreen extent -198,-170 -92,-66, body extent -194,-167 -96,-69, height 182
Keystone_1902E [mil] "Hex Standoff, 4-40 threaded, nylon"
  round 1 on Mech4: 0(0,0)
  body extent -145,-126 146,126, height 1001
Label_650x200 [mil] "Thermal Transfer Label"
  round 1 on Mech13: 0(0,0)
  silkscreen extent -325,-100 325,100, body extent -325,-100 325,100, height 1
LG_M67K_Green [mm] "SMD, 2-Leads, Body 2x1.4mm, Pitch 2mm"
  rect 0.8x1 smd mask+0: 1(-1,0) 2(1,0)
  silkscreen extent -2.1,-1 1.05,1, body extent -1.05,-0.75 1.05,0.75, height 1.4
LQH5BPN_20 [mm] "MURATA"
  rrect5% 1.85x4.1 smd: 1(-1.825,0) 2(1.825,0)
  silkscreen extent -2.5,-2.65 2.5,2.65, body extent -2.55,-2.55 2.55,2.55, height 2.2
NGG0006A [mm] "TI recommended footprint"
  rrect29% 0.6x0.35 smd: 1(-1.4,0.95) 2(-1.4,0) 3(-1.4,-0.95) 4(1.4,-0.95) 5(1.4,0) 6(1.4,0.95)
  rrect50% 1.47x0.94 on Top Paste: 7(0,0.57) 7(0,-0.57)
  rrect6% 1.6x2.1 smd paste-1: 7(0,0)
  silkscreen extent -1.65,-1.65 1.65,1.65, body extent -1.5,-1.5 1.5,1.5, height 0.81
Pb-Free_Overlay_Small [mil]
  silkscreen extent -46,-46 46,46
RNX0012B [mm] "VQFN-HR-12"
  rrect40% 0.6x0.25 smd: 1(-0.9,1.125) 2(-0.9,0.475) 3(-0.9,-0.175) 4(-0.9,-0.675) 8(0.9,-0.675) 9(0.9,-0.175) 10(0.9,0.475) 11(0.9,1.125)
  rrect40% 0.25x0.6 smd: 5(-0.5,-1.4) 6(0,-1.4) 7(0.5,-1.4)
  rrect40% 0.25x0.812 on Top Paste: 12(0,1.295) 12(0,0.28)
  rrect40% 0.25x1.825 smd paste-0.175: 12(0,0.788)
  body extent -1,-1.5 1,1.5, height 1
SIP0008A [mm] "SIP, 9-Leads, Body 2.35x2.95mm, Pitch 1mm x 0.8 mm, TI Recommended"
  round 0.3 smd paste+0.02: A1(-1,0.8) A2(0,0.8) A3(1,0.8) B1(-1,0) B2(0,0) C1(-1,-0.8) C2(0,-0.8) C3(1,-0.8)
  silkscreen extent -1.53,-1.22 1.53,1.22, body extent -1.45,-1.15 1.45,1.15, height 0.93
SIP0009F [mm] "SIP, 9-Leads, Body 2.35x2.95mm, Pitch 1mm x 1.1 mm, TI Recommended"
  round 0.3 smd paste+0.02: A1(-1,0.8) A2(0,0.8) A3(1,0.8) B1(-1,0) B2(0,0) B3(1,0) C1(-1,-0.8) C2(0,-0.8) C3(1,-0.8)
  silkscreen extent -1.53,-1.23 1.53,1.22, body extent -1.45,-1.15 1.45,1.15, height 1.1
SMA [mm] "Molded Diode, 2-Leads, Body 4.3x2.6mm, IPC Medium Density, based on OnSemi component dimensions and land pattern"
  rect 2x2 smd: 1(-2,0) 2(2,0)
  silkscreen extent -3.66,-1.57 2.79,1.57, body extent -2.6,-1.3 2.6,1.3, height 2.42
SOD-123 [mm] "On Semi recommended land pattern"
  rect 0.915x1.22 smd: 1(-1.637,0) 2(1.637,0)
  silkscreen extent -2.74,-1.17 2.03,1.17, body extent -1.93,-0.9 1.93,0.9, height 1.35
Sullins_PBC02SAAN [mm] "Sullins 100mil, 1x2, 230 mil above insulator"
  rect 1.65x1.65 hole 1.016: 1(0,1.27)
  round 1.65 hole 1.016: 2(0,-1.27)
  silkscreen extent -1.37,-2.54 1.27,3.1, body extent -1.27,-2.54 1.27,2.54, height 8.38
SW_PTS820 [mm] "SMT, 2-Leads, Body 3.9x2.9mm"
  rect 0.95x1.4 smd: 1(-2.075,0) 2(2.075,0)
  round 0.8 hole 0.8 unplated: MH1(0,0.9) MH2(0,-0.9)
  rect 1.15x0.75 smd: MP1(-1.575,1.525) MP2(1.575,1.525) MP3(1.575,-1.525) MP4(-1.575,-1.525)
  silkscreen extent -2.45,-2.2 2.45,2.2, body extent -2.25,-1.45 2.25,1.45, height 2
VLS2012ET [mm] "TDK"
  rect 0.65x2 smd: 1(-0.675,0) 2(0.675,0)
  silkscreen extent -0.15,-1.15 0.15,1.15, body extent -1.05,-1.05 1.05,1.05, height 1.2
WE-MAPI_4030 [mm] "SMD, 2-Leads, Body 4.1x4.1mm"
  rect 0.98x3.7 smd: 1(-1.185,0) 2(1.185,0)
  silkscreen extent -2.15,-2.15 2.15,2.15, body extent -2.05,-2.05 2.05,2.05, height 3.1
WE-PD-M [mm] "Wurth Elektronik recommended land pattern, 2008-01-04"
  rect 2x1.7 smd: 1(-3,0) 2(3,0)
  silkscreen extent -4.3,-4 4.3,4, body extent -3.8,-3.82 3.8,3.77, height 4.5
WE-PDF_1064 [mm] "WERTH"
  rect 2.4x3.4 smd: 1(-4.1,0) 2(4.1,0)
  silkscreen extent -5.1,-5.1 5.1,5.1, body extent -5.1,-5.1 5.1,5.1, height 6.35
WE-SPC_4838 [mm] "WURTH"
  rect 2x5.3 smd: 1(-1.75,0) 2(1.75,0)
  silkscreen extent -0.48,-2.65 0.48,2.65, body extent -2.55,-2.55 2.55,2.55, height 4.1
WE-TIS-1111 [mm] "WURTH"
  round 1.8 hole 1.016: 1(-2.5,0) 2(2.5,0)
  silkscreen extent -5.55,-5.55 5.55,5.55, body extent -5.5,-5.5 5.5,5.5, height 11.5
WE-TPC-M1 [mm] "Wurth Elektronik recommended land pattern"
  rect 0.5x0.5 smd: 1(-2.35,0) 2(2.325,0)
  Top Layer region: -0.75,1.64 -1.005,1.504 -1.279,1.279 -1.504,1.005 -1.671,0.692 -1.774,0.353 -1.809,0 -1.774,-0.353 -1.671,-0.692 -1.504,-1.005 -1.279,-1.279 -1.005,-1.504 -0.75,-1.64 -0.75,-2.65 -2.75,-2.65 -2.75,2.65 -0.75,2.65
  Top Layer region: 0.75,1.64 1.005,1.504 1.279,1.279 1.504,1.005 1.671,0.692 1.774,0.353 1.809,0 1.774,-0.353 1.671,-0.692 1.504,-1.005 1.279,-1.279 1.005,-1.504 0.75,-1.64 0.75,-2.65 2.75,-2.65 2.75,2.65 0.75,2.65
  silkscreen extent -3,-3 3,3, body extent -2.5,-2.5 2.5,2.5, height 2
WEEE_Minimum [mil] "WEEElie bin"
  silkscreen extent -95,-172 99,104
